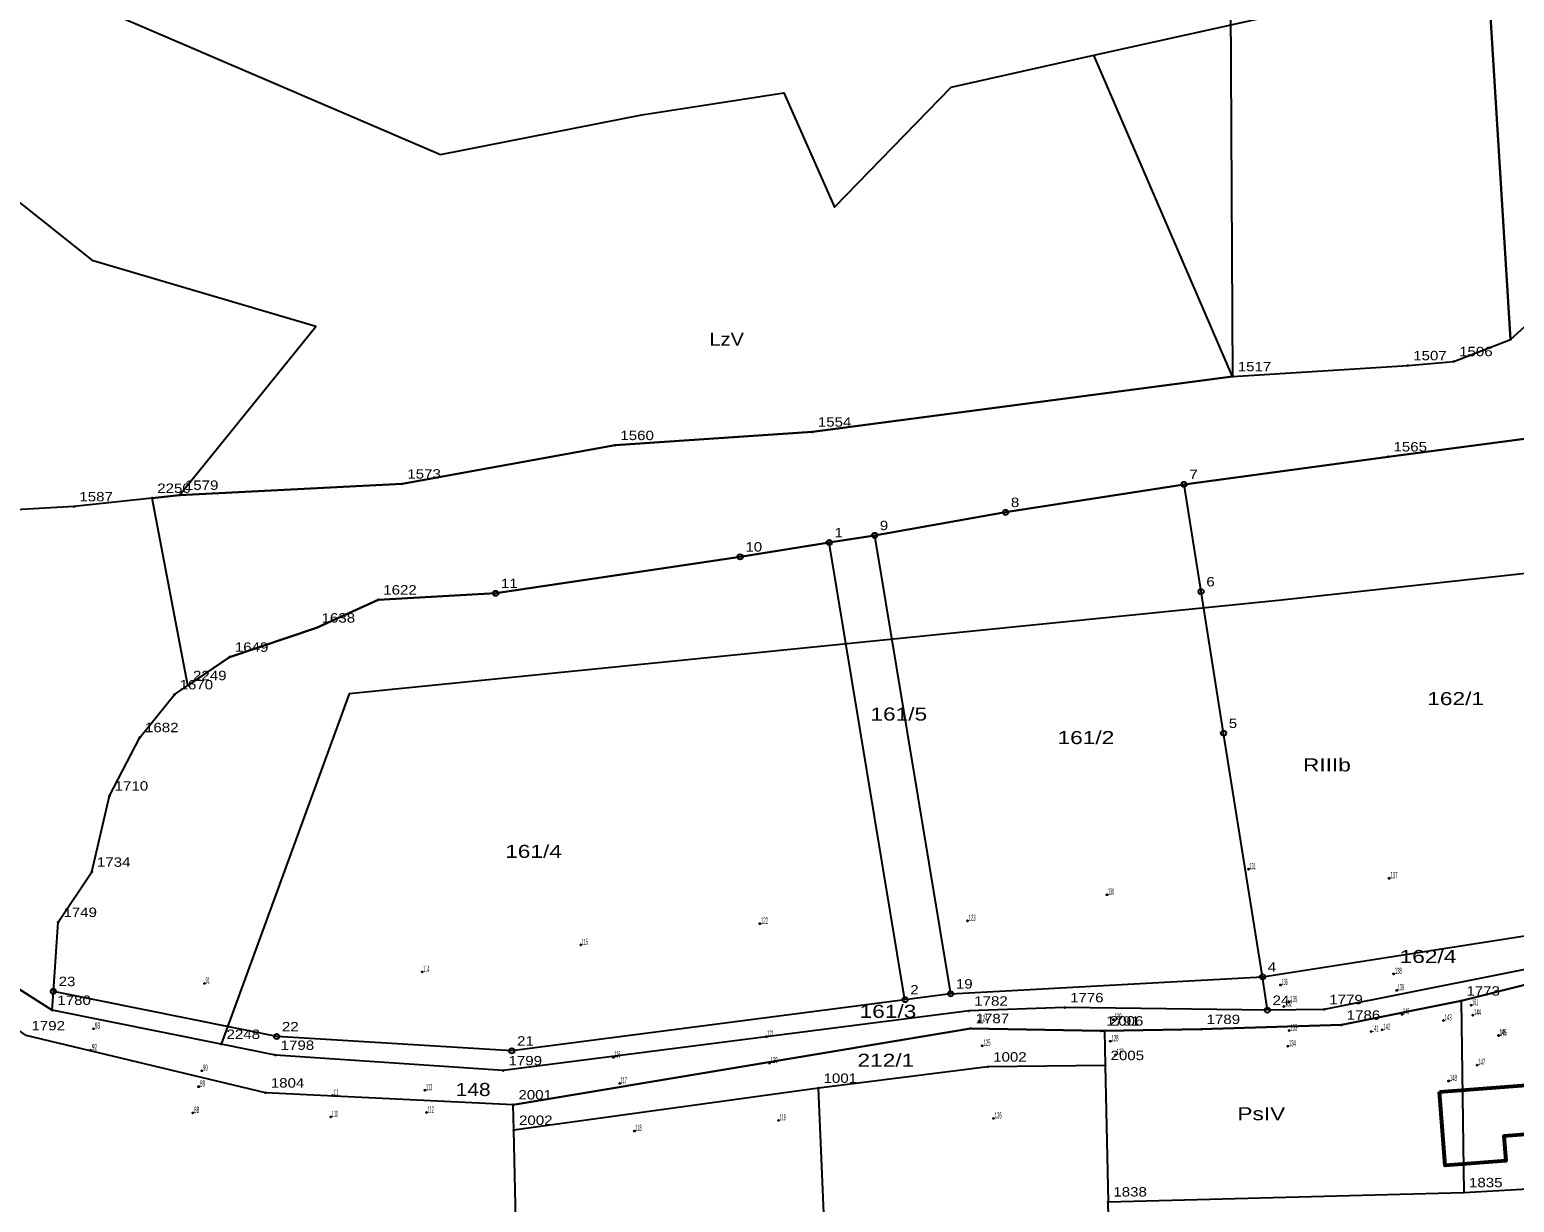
# Model space of a CAD drawing. Extents: x 4640203 to 4641683, y 5358965 to 5360242.
# Drawn here: x 4641021.5 to 4641163.8, y 5359976.5 to 5360088.9 of the extents above; entities that cross this region are included whole.
import ezdxf

# ---------------------------------------------------------------- set-up
doc = ezdxf.new("R2010")
doc.units = 0
doc.header["$LTSCALE"] = 0.36
doc.layers.add('24', color=7, linetype='Continuous')
doc.layers.add('26', color=7, linetype='Continuous')
for name, color, linetype, lineweight in [('25', 7, 'Continuous', 25), ('27', 7, 'Continuous', 25), ('3', 7, 'Continuous', 53), ('63', 7, 'Continuous', 25), ('8', 7, 'Continuous', 25)]:
    doc.layers.add(name, color=color, linetype=linetype, lineweight=lineweight)

msp = doc.modelspace()

# ---------------------------------------------------------------- linework, layer by layer
at = {"layer": '25'}
for p, q in [((4641105.41, 5359995.9), (4641098.15, 5360039.71)), ((4641140.14, 5359994.9), (4641139.68, 5359998.09))]:
    msp.add_line(p, q, dxfattribs=at)
for points in [[(4641136.45, 5360120.8), (4641136.8, 5360055.63), (4641153.61, 5360056.68), (4641158.01, 5360057.07), (4641163.42, 5360059.17), (4641161.24, 5360094.8), (4641160.06, 5360116.72), (4641159.5, 5360122.41)], [(4641012.13, 5359939.61), (4641021.04, 5359939.12), (4641069.42, 5359936.43), (4641068.41, 5359961.8), (4641067.93, 5359983.4), (4641067.87, 5359985.84), (4641044.14, 5359986.98), (4641021.21, 5359992.46), (4641014.65, 5359996.97)]]:
    msp.add_lwpolyline(points, close=True, dxfattribs=at)
for points in [[(4641136.8, 5360055.63), (4641096.56, 5360050.32), (4641077.64, 5360049.03), (4641057.23, 5360045.34), (4641035.91, 5360044.26), (4641033.26, 5360043.97), (4641025.8, 5360043.16), (4641013.49, 5360042.47), (4640971.16, 5360041.7), (4640948.43, 5360041.06), (4640946.29, 5360041.15), (4640945.41, 5360018.81)], [(4641139.68, 5359998.09), (4641170.72, 5360002.94), (4641184.53, 5360002.94), (4641181.84, 5360041.84), (4641184.84, 5360042.05), (4641184.14, 5360052.21)], [(4641023.69, 5359994.9), (4641023.81, 5359996.7), (4641024.27, 5360003.33), (4641027.48, 5360008.14), (4641029.18, 5360015.44), (4641032.09, 5360021.04), (4641035.4, 5360025.14), (4641036.69, 5360026.02), (4641040.7, 5360028.74), (4641049.01, 5360031.54), (4641054.92, 5360034.23), (4641066.2, 5360034.85), (4641089.62, 5360038.35), (4641098.15, 5360039.71), (4641102.5, 5360040.4), (4641115.06, 5360042.61), (4641132.16, 5360045.29), (4641151.72, 5360047.94), (4641173.5, 5360050.81)], [(4641102.5, 5360040.4), (4641109.79, 5359996.47), (4641139.68, 5359998.09), (4641135.94, 5360021.44), (4641133.79, 5360035.01), (4641132.16, 5360045.29)], [(4641170.92, 5360000), (4641145.57, 5359994.97), (4641140.14, 5359994.9), (4641120.73, 5359995.15), (4641111.55, 5359994.83), (4641066.92, 5359989.11), (4641045.09, 5359990.59), (4641039.9, 5359991.64), (4641023.69, 5359994.9), (4641003.17, 5360007.96)], [(4641124.54, 5359992.92), (4641124.61, 5359989.61), (4641124.88, 5359976.54), (4641158.96, 5359977.43), (4641186.91, 5359979.03), (4641212.95, 5359980.26), (4641216.55, 5359994.3), (4641216.4, 5359997.92)], [(4641109.79, 5359996.47), (4641105.41, 5359995.9), (4641067.74, 5359991), (4641045.21, 5359992.37), (4641023.81, 5359996.7)], [(4641067.87, 5359985.84), (4641111.68, 5359993.15), (4641124.19, 5359992.91), (4641124.54, 5359992.92), (4641133.81, 5359993.07), (4641147.24, 5359993.48), (4641158.71, 5359995.79), (4641164.93, 5359997.35)], [(4641124.61, 5359989.61), (4641113.36, 5359989.47), (4641097.11, 5359987.43)], [(4641099.32, 5359935.66), (4641097.11, 5359987.43), (4641067.93, 5359983.4)], [(4641127.04, 5359934.94), (4641124.91, 5359975.06), (4641124.88, 5359976.54)]]:
    msp.add_lwpolyline(points, dxfattribs=at)
at = {"layer": '27'}
for points in [[(4641013.42, 5360089.21), (4641024.2, 5360092.67), (4641060.92, 5360076.91), (4641080.2, 5360080.7), (4641093.8, 5360082.81), (4641098.67, 5360071.84), (4641109.85, 5360083.35), (4641123.5, 5360086.41), (4641161.24, 5360094.8), (4641160.41, 5360097.78), (4641159.1, 5360108.61), (4641158.42, 5360117.59), (4641138.82, 5360116.94), (4641091.35, 5360111.38), (4641087.73, 5360122.42), (4641072.96, 5360120.88), (4641039.99, 5360116.64), (4641030.67, 5360116.09), (4641016.16, 5360109.22)], [(4641256.47, 5360097.81), (4641247.03, 5360099.15), (4641232.91, 5360100.84), (4641215.68, 5360091.36), (4641196.97, 5360092.27), (4641179.55, 5360092.08), (4641161.24, 5360094.8), (4641163.42, 5360059.17), (4641170.79, 5360065.86), (4641185.64, 5360069.11), (4641189.99, 5360066.54), (4641199.88, 5360066.6), (4641211.17, 5360072.59), (4641224.24, 5360075.65), (4641233.66, 5360076.96), (4641245.4, 5360078.58), (4641254.72, 5360078.07), (4641265.56, 5360080.37)], [(4641035.91, 5360044.26), (4641057.23, 5360045.34), (4641077.64, 5360049.03), (4641096.56, 5360050.32), (4641136.8, 5360055.63), (4641123.5, 5360086.41)], [(4641033.26, 5360043.97), (4641035.91, 5360044.26), (4641048.96, 5360060.42), (4641027.63, 5360066.71), (4641008.94, 5360081.56)], [(4641233.82, 5360044.27), (4641241.7, 5360065.97), (4641217, 5360061.94), (4641195.49, 5360053.71), (4641184.14, 5360052.21), (4641173.5, 5360050.81), (4641151.72, 5360047.94), (4641132.16, 5360045.29), (4641115.06, 5360042.61), (4641102.5, 5360040.4), (4641098.15, 5360039.71), (4641089.62, 5360038.35), (4641066.2, 5360034.85), (4641054.92, 5360034.23), (4641049.01, 5360031.54), (4641040.7, 5360028.74), (4641036.69, 5360026.02)], [(4640945.41, 5360018.81), (4640946.99, 5360018.68), (4640962.99, 5360018.69), (4640975.8, 5360017.77), (4640985.12, 5360015.34), (4641003.17, 5360007.96), (4641023.69, 5359994.9), (4641023.81, 5359996.7), (4641024.27, 5360003.33), (4641027.48, 5360008.14), (4641029.18, 5360015.44), (4641032.09, 5360021.04), (4641035.4, 5360025.14), (4641036.69, 5360026.02), (4641033.26, 5360043.97), (4641025.8, 5360043.16), (4641013.49, 5360042.47), (4640971.16, 5360041.7), (4640948.43, 5360041.06), (4640946.29, 5360041.15)], [(4641216.31, 5360000.2), (4641216.18, 5360002.94), (4641216.03, 5360006.8), (4641222.35, 5360011.68), (4641230.52, 5360035.19), (4641233.82, 5360044.27), (4641141.19, 5360034.16), (4641052.15, 5360025.2), (4641039.9, 5359991.64)], [(4641124.54, 5359992.92), (4641124.19, 5359992.91), (4641111.68, 5359993.15), (4641067.87, 5359985.84), (4641044.14, 5359986.98), (4641021.21, 5359992.46), (4641014.65, 5359996.97), (4641001.58, 5360005.95), (4640996.56, 5360008.11), (4640984.63, 5360012.43), (4640971.51, 5360015.64), (4640961.41, 5360016.58), (4640945.71, 5360015.87), (4640943.53, 5360016.15), (4640936.1, 5360017.1), (4640926.51, 5360016.14), (4640916.11, 5360016.57), (4640906.7, 5360017.91), (4640904.69, 5360018.38), (4640900.85, 5359995.67), (4640899.67, 5359987.05)], [(4641186.49, 5359998.68), (4641190.9, 5359998.59), (4641200.47, 5359998.36), (4641210.85, 5359997.49), (4641212.9, 5359997.85), (4641216.4, 5359997.92), (4641216.31, 5360000.2), (4641211.02, 5359998.67), (4641201.52, 5360000), (4641192.12, 5359999.98), (4641190.75, 5359999.98), (4641184.73, 5359999.98), (4641170.92, 5360000), (4641145.57, 5359994.97), (4641140.14, 5359994.9), (4641120.73, 5359995.15), (4641111.55, 5359994.83), (4641066.92, 5359989.11), (4641045.09, 5359990.59), (4641039.9, 5359991.64), (4641023.69, 5359994.9)], [(4641158.71, 5359995.79), (4641147.24, 5359993.48), (4641133.81, 5359993.07), (4641124.54, 5359992.92)], [(4641124.54, 5359992.92), (4641124.61, 5359989.61), (4641124.88, 5359976.54), (4641158.96, 5359977.43)]]:
    msp.add_lwpolyline(points, dxfattribs=at)
msp.add_lwpolyline([(4641158.71, 5359995.79), (4641158.96, 5359977.43), (4641186.91, 5359979.03), (4641186.81, 5359983.04), (4641186.13, 5359992.94), (4641186.49, 5359998.68), (4641180.02, 5359998.81), (4641164.93, 5359997.35)], close=True, dxfattribs=at)
at = {"layer": '3'}
msp.add_lwpolyline([(4641156.63, 5359987.06), (4641170.76, 5359988.16), (4641171.13, 5359983.46), (4641162.8, 5359982.81), (4641162.98, 5359980.47), (4641157.17, 5359980.02)], close=True, dxfattribs=at)
at = {"layer": '63'}
for centre in [(4641138.32, 5360008.41), (4641138.32, 5360008.41), (4641151.82, 5360007.53), (4641151.82, 5360007.53), (4641124.77, 5360005.96), (4641124.77, 5360005.96), (4641091.51, 5360003.19), (4641091.51, 5360003.19), (4641111.4, 5360003.46), (4641111.4, 5360003.46), (4641074.35, 5360001.16), (4641074.35, 5360001.16), (4641059.15, 5359998.56), (4641059.15, 5359998.56), (4641152.24, 5359998.37), (4641152.24, 5359998.37), (4641038.3, 5359997.46), (4641038.3, 5359997.46), (4641141.4, 5359997.31), (4641141.4, 5359997.31), (4641152.54, 5359996.8), (4641152.54, 5359996.8), (4641141.72, 5359995.25), (4641141.72, 5359995.25), (4641142.23, 5359995.67), (4641142.23, 5359995.67), (4641159.66, 5359995.37), (4641159.66, 5359995.37), (4641112.54, 5359993.83), (4641112.54, 5359993.83), (4641125.39, 5359993.99), (4641125.39, 5359993.99), (4641153.05, 5359994.5), (4641153.05, 5359994.5), (4641157.01, 5359993.91), (4641157.01, 5359993.91), (4641159.83, 5359994.42), (4641159.83, 5359994.42), (4641027.66, 5359993.12), (4641027.66, 5359993.12), (4641092.13, 5359992.36), (4641092.13, 5359992.36), (4641142.23, 5359992.94), (4641142.23, 5359992.94), (4641150.09, 5359992.85), (4641150.09, 5359992.85), (4641151.14, 5359993.02), (4641151.14, 5359993.02), (4641162.3, 5359992.48), (4641162.3, 5359992.48), (4641162.3, 5359992.47), (4641162.3, 5359992.47), (4641027.37, 5359991.06), (4641027.37, 5359991.06), (4641112.82, 5359991.49), (4641112.82, 5359991.49), (4641125.09, 5359991.92), (4641125.09, 5359991.92), (4641142.09, 5359991.44), (4641142.09, 5359991.44), (4641077.47, 5359990.38), (4641077.47, 5359990.38), (4641092.42, 5359989.82), (4641092.42, 5359989.82), (4641125.58, 5359990.62), (4641125.58, 5359990.62), (4641160.23, 5359989.64), (4641160.23, 5359989.64), (4641038.04, 5359989.09), (4641038.04, 5359989.09), (4641078.08, 5359987.88), (4641078.08, 5359987.88), (4641157.51, 5359988.11), (4641157.51, 5359988.11), (4641037.73, 5359987.57), (4641037.73, 5359987.57), (4641050.55, 5359986.72), (4641050.55, 5359986.72), (4641059.42, 5359987.22), (4641059.42, 5359987.22), (4641037.16, 5359985.05), (4641037.16, 5359985.05), (4641059.57, 5359985.09), (4641059.57, 5359985.09), (4641050.4, 5359984.67), (4641050.4, 5359984.67), (4641093.3, 5359984.33), (4641093.3, 5359984.33), (4641113.9, 5359984.52), (4641113.9, 5359984.52), (4641079.49, 5359983.32), (4641079.49, 5359983.32)]:
    msp.add_circle(centre, 0.05, dxfattribs=at)
at = {"layer": '8'}
for centre, radius in [((4641163.42, 5360059.17), 0.045), ((4641153.61, 5360056.68), 0.045), ((4641158.01, 5360057.07), 0.045), ((4641136.8, 5360055.63), 0.045), ((4641096.56, 5360050.32), 0.045), ((4641077.64, 5360049.03), 0.045), ((4641151.72, 5360047.94), 0.045), ((4641057.23, 5360045.34), 0.045), ((4641132.16, 5360045.29), 0.25), ((4641033.26, 5360043.97), 0.045), ((4641035.91, 5360044.26), 0.045), ((4641025.8, 5360043.16), 0.045), ((4641115.06, 5360042.61), 0.25), ((4641102.5, 5360040.4), 0.25), ((4641098.15, 5360039.71), 0.25), ((4641089.62, 5360038.35), 0.25), ((4641066.2, 5360034.85), 0.25), ((4641133.79, 5360035.01), 0.25), ((4641054.92, 5360034.23), 0.045), ((4641049.01, 5360031.54), 0.045), ((4641040.7, 5360028.74), 0.045), ((4641035.4, 5360025.14), 0.045), ((4641036.69, 5360026.02), 0.045), ((4641032.09, 5360021.04), 0.045), ((4641135.94, 5360021.44), 0.25), ((4641029.18, 5360015.44), 0.045), ((4641027.48, 5360008.14), 0.045), ((4641024.27, 5360003.33), 0.045), ((4641139.68, 5359998.09), 0.25), ((4641023.81, 5359996.7), 0.25), ((4641109.79, 5359996.47), 0.25), ((4641105.41, 5359995.9), 0.25), ((4641120.73, 5359995.15), 0.045), ((4641140.14, 5359994.9), 0.25), ((4641158.71, 5359995.79), 0.045), ((4641023.69, 5359994.9), 0.045), ((4641111.55, 5359994.83), 0.045), ((4641145.57, 5359994.97), 0.045), ((4641045.21, 5359992.37), 0.25), ((4641111.68, 5359993.15), 0.045), ((4641124.19, 5359992.91), 0.045), ((4641124.54, 5359992.92), 0.045), ((4641133.81, 5359993.07), 0.045), ((4641147.24, 5359993.48), 0.045), ((4641039.9, 5359991.64), 0.045), ((4641067.74, 5359991), 0.25), ((4641045.09, 5359990.59), 0.045), ((4641113.36, 5359989.47), 0.045), ((4641124.61, 5359989.61), 0.045), ((4641066.92, 5359989.11), 0.045), ((4641044.14, 5359986.98), 0.045), ((4641097.11, 5359987.43), 0.045), ((4641067.87, 5359985.84), 0.045), ((4641067.93, 5359983.4), 0.045), ((4641124.88, 5359976.54), 0.045), ((4641158.96, 5359977.43), 0.045)]:
    msp.add_circle(centre, radius, dxfattribs=at)

# ---------------------------------------------------------------- texts
at = {"layer": '24'}
for s, width, p in [('162/1', 1.3, (4641155.46, 5360024.13)), ('161/5', 1.3, (4641102.1, 5360022.65)), ('161/2', 1.3, (4641120.03, 5360020.4)), ('161/4', 1.3, (4641067.1, 5360009.49)), ('162/4', 1.3, (4641152.81, 5359999.42)), ('161/3', 1.3, (4641101.06, 5359994.16)), ('212/1', 1.3, (4641100.86, 5359989.47)), ('148', 1.2, (4641062.36, 5359986.67))]:
    msp.add_text(s, height=1.25, dxfattribs=dict(at, width=width)).set_placement(p)
at = {"layer": '26'}
for s, width, p in [('LzV', 1.15, (4641086.67, 5360058.58)), ('RIIIb', 1.3, (4641143.55, 5360017.78)), ('PsIV', 1.3, (4641137.26, 5359984.35))]:
    msp.add_text(s, height=1.25, dxfattribs=dict(at, width=width)).set_placement(p)
at = {"layer": '63'}
for s, width, p in [(' 131', 0.35, (4641138.32, 5360008.41)), (' 131', 0.35, (4641138.32, 5360008.41)), (' 137', 0.4, (4641151.82, 5360007.53)), (' 137', 0.4, (4641151.82, 5360007.53)), (' 130', 0.35, (4641124.77, 5360005.96)), (' 130', 0.35, (4641124.77, 5360005.96)), (' 122', 0.4, (4641091.51, 5360003.19)), (' 122', 0.4, (4641091.51, 5360003.19)), (' 123', 0.4, (4641111.4, 5360003.46)), (' 123', 0.4, (4641111.4, 5360003.46)), (' 115', 0.35, (4641074.35, 5360001.16)), (' 115', 0.35, (4641074.35, 5360001.16)), (' 91', 0.35, (4641038.3, 5359997.46)), (' 91', 0.35, (4641038.3, 5359997.46)), (' 114', 0.35, (4641059.15, 5359998.56)), (' 114', 0.35, (4641059.15, 5359998.56)), (' 136', 0.35, (4641141.4, 5359997.31)), (' 136', 0.35, (4641141.4, 5359997.31)), (' 138', 0.4, (4641152.24, 5359998.37)), (' 138', 0.4, (4641152.24, 5359998.37)), (' 139', 0.35, (4641152.54, 5359996.8)), (' 139', 0.35, (4641152.54, 5359996.8)), (' 132', 0.4, (4641141.72, 5359995.25)), (' 132', 0.4, (4641141.72, 5359995.25)), (' 135', 0.4, (4641142.23, 5359995.67)), (' 135', 0.4, (4641142.23, 5359995.67)), (' 140', 0.35, (4641153.05, 5359994.5)), (' 140', 0.35, (4641153.05, 5359994.5)), (' 161', 0.35, (4641159.66, 5359995.37)), (' 161', 0.35, (4641159.66, 5359995.37)), (' 93', 0.45, (4641027.66, 5359993.12)), (' 93', 0.45, (4641027.66, 5359993.12)), (' 124', 0.4, (4641112.54, 5359993.83)), (' 124', 0.4, (4641112.54, 5359993.83)), (' 129', 0.4, (4641125.39, 5359993.99)), (' 129', 0.4, (4641125.39, 5359993.99)), (' 142', 0.4, (4641151.14, 5359993.02)), (' 142', 0.4, (4641151.14, 5359993.02)), (' 143', 0.4, (4641157.01, 5359993.91)), (' 143', 0.4, (4641157.01, 5359993.91)), (' 144', 0.4, (4641159.83, 5359994.42)), (' 144', 0.4, (4641159.83, 5359994.42)), (' 121', 0.35, (4641092.13, 5359992.36)), (' 121', 0.35, (4641092.13, 5359992.36)), (' 128', 0.4, (4641125.09, 5359991.92)), (' 128', 0.4, (4641125.09, 5359991.92)), (' 133', 0.4, (4641142.23, 5359992.94)), (' 133', 0.4, (4641142.23, 5359992.94)), (' 141', 0.35, (4641150.09, 5359992.85)), (' 141', 0.35, (4641150.09, 5359992.85)), (' 146', 0.35, (4641162.3, 5359992.48)), (' 146', 0.35, (4641162.3, 5359992.48)), (' 145', 0.4, (4641162.3, 5359992.47)), (' 145', 0.4, (4641162.3, 5359992.47)), (' 92', 0.45, (4641027.37, 5359991.06)), (' 92', 0.45, (4641027.37, 5359991.06)), (' 116', 0.35, (4641077.47, 5359990.38)), (' 116', 0.35, (4641077.47, 5359990.38)), (' 125', 0.4, (4641112.82, 5359991.49)), (' 125', 0.4, (4641112.82, 5359991.49)), (' 127', 0.4, (4641125.58, 5359990.62)), (' 127', 0.4, (4641125.58, 5359990.62)), (' 134', 0.4, (4641142.09, 5359991.44)), (' 134', 0.4, (4641142.09, 5359991.44)), (' 90', 0.4, (4641038.04, 5359989.09)), (' 90', 0.4, (4641038.04, 5359989.09)), (' 120', 0.4, (4641092.42, 5359989.82)), (' 120', 0.4, (4641092.42, 5359989.82)), (' 147', 0.4, (4641160.23, 5359989.64)), (' 147', 0.4, (4641160.23, 5359989.64)), (' 89', 0.45, (4641037.73, 5359987.57)), (' 89', 0.45, (4641037.73, 5359987.57)), (' 117', 0.35, (4641078.08, 5359987.88)), (' 117', 0.35, (4641078.08, 5359987.88)), (' 148', 0.4, (4641157.51, 5359988.11)), (' 148', 0.4, (4641157.51, 5359988.11)), (' 111', 0.3, (4641050.55, 5359986.72)), (' 111', 0.3, (4641050.55, 5359986.72)), (' 113', 0.35, (4641059.42, 5359987.22)), (' 113', 0.35, (4641059.42, 5359987.22)), (' 88', 0.45, (4641037.16, 5359985.05)), (' 88', 0.45, (4641037.16, 5359985.05)), (' 110', 0.35, (4641050.4, 5359984.67)), (' 110', 0.35, (4641050.4, 5359984.67)), (' 112', 0.35, (4641059.57, 5359985.09)), (' 112', 0.35, (4641059.57, 5359985.09)), (' 126', 0.4, (4641113.9, 5359984.52)), (' 126', 0.4, (4641113.9, 5359984.52)), (' 118', 0.35, (4641079.49, 5359983.32)), (' 118', 0.35, (4641079.49, 5359983.32)), (' 119', 0.35, (4641093.3, 5359984.33)), (' 119', 0.35, (4641093.3, 5359984.33))]:
    msp.add_text(s, height=0.6, dxfattribs=dict(at, width=width)).set_placement(p)
at = {"layer": '8', "width": 1.2}
for s, p in [('1507', (4641154.11, 5360057.18)), ('1506', (4641158.51, 5360057.57)), ('1517', (4641137.3, 5360056.13)), ('1554', (4641097.06, 5360050.82)), ('1560', (4641078.14, 5360049.53)), ('1565', (4641152.22, 5360048.44)), ('1573', (4641057.73, 5360045.84)), ('7', (4641132.66, 5360045.79)), ('2250', (4641033.76, 5360044.47)), ('1579', (4641036.41, 5360044.76)), ('1587', (4641026.3, 5360043.66)), ('8', (4641115.56, 5360043.11)), ('1', (4641098.65, 5360040.21)), ('9', (4641103, 5360040.9)), ('10', (4641090.12, 5360038.85)), ('6', (4641134.29, 5360035.51)), ('1622', (4641055.42, 5360034.73)), ('11', (4641066.7, 5360035.35)), ('1638', (4641049.51, 5360032.04)), ('1649', (4641041.2, 5360029.24)), ('1670', (4641035.9, 5360025.64)), ('2249', (4641037.19, 5360026.52)), ('1682', (4641032.59, 5360021.54)), ('5', (4641136.44, 5360021.94)), ('1710', (4641029.68, 5360015.94)), ('1734', (4641027.98, 5360008.64)), ('1749', (4641024.77, 5360003.83)), ('4', (4641140.18, 5359998.59)), ('23', (4641024.31, 5359997.2)), ('19', (4641110.29, 5359996.97)), ('2', (4641105.91, 5359996.4)), ('1776', (4641121.23, 5359995.65)), ('1773', (4641159.21, 5359996.29)), ('1780', (4641024.19, 5359995.4)), ('1782', (4641112.05, 5359995.33)), ('24', (4641140.64, 5359995.4)), ('1779', (4641146.07, 5359995.47)), ('1792', (4641021.71, 5359992.96)), ('22', (4641045.71, 5359992.87)), ('1787', (4641112.18, 5359993.65)), ('1791', (4641124.69, 5359993.41)), ('2006', (4641125.04, 5359993.42)), ('1789', (4641134.31, 5359993.57)), ('1786', (4641147.74, 5359993.98)), ('2248', (4641040.4, 5359992.14)), ('21', (4641068.24, 5359991.5)), ('1798', (4641045.59, 5359991.09)), ('1002', (4641113.86, 5359989.97)), ('2005', (4641125.11, 5359990.11)), ('1799', (4641067.42, 5359989.61)), ('1804', (4641044.64, 5359987.48)), ('1001', (4641097.61, 5359987.93)), ('2001', (4641068.37, 5359986.34)), ('2002', (4641068.43, 5359983.9)), ('1838', (4641125.38, 5359977.04)), ('1835', (4641159.46, 5359977.93))]:
    msp.add_text(s, height=0.9, dxfattribs=at).set_placement(p)

doc.saveas('drawing.dxf')
